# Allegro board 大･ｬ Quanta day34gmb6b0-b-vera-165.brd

Outline 205.8 x 192.8 mm; copper layers: TOP, SGND, IN1, IN2, SVCC, BOTTOM. Coordinates in mm from the lower left corner of the outline.
Outline path: circle c65.95,125.9 r29 ; 0,89.7 0,88.9 arc(0.2,88.29) 0.73,87.94 arc(0.99,87.77) 1.1,87.48 arc(1.19,87.28) 1.4,87.2 3.3,87.2 3.3,87.4 arc(3.45,87.75) 3.8,87.9 7.7,87.9 arc(8.2,88.4) 8.7,87.9 8.7,72.5 arc(8.2,72) 7.7,72.5 3.8,72.5 arc(3.45,72.65) 3.3,73 3.3,73.2 1.4,73.2 arc(1.19,73.12) 1.1,72.92 arc(0.99,72.63) 0.73,72.46 arc(0.2,72.11) 0,71.5 0,70.61 arc(0.29,69.9) 1,69.61 1.8,69.61 arc(2.51,69.32) 2.8,68.61 2.8,68.45 arc(3.09,67.74) 3.8,67.45 11.89,67.45 arc(12.29,67.85) 12.69,67.45 12.69,53.95 arc(12.29,53.55) 11.89,53.95 3.8,53.95 arc(3.09,53.66) 2.8,52.95 2.8,51.45 arc(3.09,50.74) 3.8,50.45 11.89,50.45 arc(12.29,50.85) 12.69,50.45 12.69,36.95 arc(12.29,36.55) 11.89,36.95 3.8,36.95 arc(3.09,36.66) 2.8,35.95 2.8,33.47 arc(3.09,32.76) 3.8,32.47 4.3,32.47 arc(5.01,32.18) 5.3,31.47 5.3,11.97 arc(5.01,11.26) 4.3,10.97 3.8,10.97 arc(3.09,10.68) 2.8,9.97 2.8,8.24 arc(3.03,7.09) 3.68,6.12 8.92,0.88 arc(9.89,0.23) 11.04,0 24.8,0 arc(25.51,0.29) 25.8,1 25.8,4 arc(26.09,4.71) 26.8,5 40.8,5 arc(41.51,5.29) 41.8,6 41.8,8 arc(42.09,8.71) 42.8,9 58.8,9 arc(59.51,8.71) 59.8,8 59.8,3.5 arc(60.09,2.79) 60.8,2.5 97.8,2.5 arc(98.51,2.21) 98.8,1.5 98.8,1 arc(99.09,0.29) 99.8,0 102.8,0 arc(103.51,0.29) 103.8,1 103.8,1.5 arc(104.09,2.21) 104.8,2.5 192.3,2.5 arc(193.01,2.79) 193.3,3.5 193.3,5 arc(193.59,5.71) 194.3,6 201.8,6 arc(204.63,7.17) 205.8,10 205.8,61 202.35,61 202.35,77.25 arc(202.48,77.75) 202.85,78.11 arc(203.22,78.48) 203.35,78.98 203.35,108.4 arc(203.06,109.11) 202.35,109.4 201.5,109.4 201.5,146.79 195.5,146.79 195.5,155.39 201.5,155.39 201.5,164.89 183.85,164.89 183.85,164.39 arc(183.7,164.04) 183.35,163.89 180.95,163.89 arc(180.6,164.04) 180.45,164.39 180.45,164.89 169.9,164.89 169.9,190.8 arc(169.31,192.21) 167.9,192.8 95.8,192.8 arc(94.74,192.36) 94.3,191.3 94.3,189.2 arc(94.01,188.49) 93.3,188.2 86.04,188.2 arc(85.81,188.17) 85.59,188.09 84.35,187.48 arc(83.95,187.11) 83.8,186.58 83.8,185.2 arc(83.51,184.49) 82.8,184.2 80.8,184.2 arc(80.09,184.49) 79.8,185.2 79.8,186.58 arc(79.65,187.11) 79.25,187.48 78.01,188.09 arc(77.79,188.17) 77.56,188.2 69.6,188.2 arc(68.89,187.91) 68.6,187.2 68.6,186.7 arc(68.31,185.99) 67.6,185.7 38.3,185.7 arc(37.59,185.99) 37.3,186.7 37.3,188.5 arc(37.01,189.21) 36.3,189.5 27.3,189.5 arc(26.59,189.21) 26.3,188.5 26.3,181.2 arc(26.01,180.49) 25.3,180.2 17.3,180.2 arc(16.59,180.49) 16.3,181.2 16.3,184.2 arc(16.01,184.91) 15.3,185.2 10.3,185.2 arc(9.59,184.91) 9.3,184.2 9.3,180.6 arc(9.01,179.89) 8.3,179.6 3.8,179.6 arc(3.09,179.31) 2.8,178.6 2.8,177.99 arc(3.09,177.28) 3.8,176.99 10.08,176.99 arc(10.43,176.84) 10.58,176.49 10.58,174.6 arc(10.73,174.25) 11.08,174.1 11.42,174.1 arc(11.77,173.95) 11.92,173.6 11.92,163.8 arc(11.77,163.45) 11.42,163.3 11.08,163.3 arc(10.73,163.15) 10.58,162.8 10.58,160.91 arc(10.43,160.56) 10.08,160.41 3.8,160.41 arc(3.09,160.12) 2.8,159.41 2.8,158.5 arc(3.09,157.79) 3.8,157.5 10.8,157.5 arc(11.51,157.21) 11.8,156.5 11.8,91.7 arc(11.51,90.99) 10.8,90.7 1,90.7 arc(0.29,90.41) 0,89.7

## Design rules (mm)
constraint set DEFAULT: min track width 0.127
net group DFP-S10W10-T12B: nets DDR_THERMDA DDR_THERMDC
net group DFP-S20W10(10)-T12B: nets LINEOUT_L_C LINEOUT_R_C
net group W5-T1B: nets RTC_X1 RTC_X2
net group W20-T1B: nets SMDDR_VREF_DQ0_M3 SMDDR_VREF_DQ1_M3
net group DFP-S4(5)W5(5.5)-T1B: nets C_IN_CLK C_IN_CLK# C_TX0_HDMI+ C_TX0_HDMI- C_TX1_HDMI+ C_TX1_HDMI- C_TX2_HDMI+ C_TX2_HDMI- C_TXC_HDMI+ C_TXC_HDMI- HDMI_SCLK HDMI_SDATA IN_CLK IN_CLK# IN_D0 IN_D0# IN_D1 IN_D1# IN_D2 IN_D2# INT_EDP_AUXN INT_EDP_AUXN_R INT_EDP_AUXP INT_EDP_AUXP_R INT_EDP_TXN0 INT_EDP_TXN0_R INT_EDP_TXN1 INT_EDP_TXN1_R INT_EDP_TXP0 INT_EDP_TXP0_R INT_EDP_TXP1 INT_EDP_TXP1_R PCIE_RXN3_WLAN PCIE_RXN4_LAN PCIE_RXN4_LAN_L PCIE_RXN5_CARD PCIE_RXN5_CARD_C PCIE_RXP3_WLAN PCIE_RXP4_LAN PCIE_RXP4_LAN_L PCIE_RXP5_CARD PCIE_RXP5_CARD_C PCIE_TXN3_WLAN PCIE_TXN3_WLAN_C PCIE_TXN4_LAN PCIE_TXN4_LAN_C PCIE_TXN5_CARD PCIE_TXN5_CARD_C PCIE_TXP3_WLAN PCIE_TXP3_WLAN_C PCIE_TXP4_LAN PCIE_TXP4_LAN_C PCIE_TXP5_CARD PCIE_TXP5_CARD_C SATA_RXN0 SATA_RXN0_17 SATA_RXN1 SATA_RXN1_NG SATA_RXN1_NG_C SATA_RXN1_SSD SATA_RXN2 SATA_RXN2_15 SATA_RXP0 SATA_RXP0_17 SATA_RXP1 SATA_RXP1_NG SATA_RXP1_NG_C SATA_RXP1_SSD SATA_RXP2 SATA_RXP2_15 SATA_TXN0 SATA_TXN0_17 SATA_TXN1 SATA_TXN1_NG SATA_TXN1_NG_C SATA_TXN1_SSD SATA_TXN2 SATA_TXN2_15 SATA_TXP0 SATA_TXP0_17 SATA_TXP1 SATA_TXP1_NG SATA_TXP1_NG_C SATA_TXP1_SSD SATA_TXP2 SATA_TXP2_15 SDVO_CLK SDVO_DATA USB3_1+ USB3_1- USB3_2+ USB3_2- USB3_SSRX+ USB3_SSRX+_DC USB3_SSRX- USB3_SSRX-_DC USB3_SSTX+ USB3_SSTX+_DC USB3_SSTX- USB3_SSTX-_DC USB30_RX1+ USB30_RX1+_C USB30_RX1+_DC USB30_RX1+_L USB30_RX1- USB30_RX1-_C USB30_RX1-_DC USB30_RX1-_L USB30_RX2+ USB30_RX2+_C USB30_RX2- USB30_RX2-_C USB30_RX3+ USB30_RX3+_C USB30_RX3+_DC USB30_RX3- USB30_RX3-_C USB30_RX3-_DC USB30_RX4+ USB30_RX4- USB30_TX1+ USB30_TX1+_C USB30_TX1+_DC USB30_TX1+_L USB30_TX1- USB30_TX1-_C USB30_TX1-_DC USB30_TX1-_L USB30_TX2+ USB30_TX2+_C USB30_TX2- USB30_TX2-_C USB30_TX3+ USB30_TX3+_C USB30_TX3+_DC USB30_TX3+_DC_L USB30_TX3- USB30_TX3-_C USB30_TX3-_DC USB30_TX3-_DC_L USB30_TX4+ USB30_TX4- USBP0+ USBP0+_C USBP0+_CHA USBP0- USBP0-_C USBP0-_CHA USBP1+ USBP1+_C USBP1- USBP1-_C USBP3+ USBP3+_C USBP3- USBP3-_C USBP4+ USBP4+_C USBP4- USBP4-_C USBP5+ USBP5+_C USBP5- USBP5-_C USBP6+ USBP6- USBP7+ USBP7+_C USBP7- USBP7-_C
net group DFP-S4(5)W5(5.5)-T12B: nets M_A_CLKN0 M_A_CLKN1 M_A_CLKP0 M_A_CLKP1 M_A_DQSN0 M_A_DQSN1 M_A_DQSN2 M_A_DQSN3 M_A_DQSN4 M_A_DQSN5 M_A_DQSN6 M_A_DQSN7 M_A_DQSP0 M_A_DQSP1 M_A_DQSP2 M_A_DQSP3 M_A_DQSP4 M_A_DQSP5 M_A_DQSP6 M_A_DQSP7 M_B_CLKN0 M_B_CLKN1 M_B_CLKP0 M_B_CLKP1 M_B_DQSN0 M_B_DQSN1 M_B_DQSN2 M_B_DQSN3 M_B_DQSN4 M_B_DQSN5 M_B_DQSN6 M_B_DQSN7 M_B_DQSP0 M_B_DQSP1 M_B_DQSP2 M_B_DQSP3 M_B_DQSP4 M_B_DQSP5 M_B_DQSP6 M_B_DQSP7
net group DFP-S5(7)W5(5.5)-T1B: nets CK_XDP_N CK_XDP_N_R CK_XDP_P CK_XDP_P_R CLK_PCIE_CRN CLK_PCIE_CRP CLK_PCIE_LANN CLK_PCIE_LANP CLK_PCIE_WLANN CLK_PCIE_WLANP
net group DFP-S10W25-T12B: nets SUB_OUT+ SUB_OUT+_L SUB_OUT+_L_4P SUB_OUT+_L_C SUB_OUT+_R_C SUB_OUT- SUB_OUT-_L SUB_OUT-_L_4P SUB_OUT-_L_C SUB_OUT-_R_C SUB_OUT_LC SUB_OUT_LR SUB_OUT_RC SUB_OUT_RR
net group DFP-S12(15)W5(5.5)-T1B: nets MDI0+ MDI0+_1 MDI0- MDI0-_1 MDI1+ MDI1+_1 MDI1- MDI1-_1 MDI2+ MDI2+_1 MDI2- MDI2-_1 MDI3+ MDI3+_1 MDI3- MDI3-_1
net group W4-T12B: nets LAD0 LAD0_T LAD1 LAD1_T LAD2 LAD2_T LAD3 LAD3_T LFRAME# LFRAME#_T
net group W5(5.5)-T1B: nets ACZ_BCLK BIOS_SPI_CLK BIT_CLK_AUDIO BLON_CON BRIGHT CLK_24M_DEBUG CLK_24M_KBC CLK_PCI_EC_R CLK_PCI_LPC_R CLK_PCI_TPM CLKGEN_RTC_X1 DDR3_DRAMRST# EC_PECI EC_PECI_R EC_PWROK EC_RCIN# GEN_XTAL25_IN GEN_XTAL25_OUT H_CPU_SVIDALRT# H_PROCHOT# H_PROCHOT#_EC LAN_XTAL25_IN LAN_XTAL25_IN_R LVDS_BLON1 MS_BS MS_D0 MS_D1 MS_D2 MS_D3 PCH_SPI1_CLK PCH_SPI1_CLK_R PCH_XTAL24_IN PCH_XTAL24_IN_R PCIE_CLKREQ0# PCIE_CLKREQ1# PCIE_CLKREQ5# PCIE_CLKREQ_CR# PCIE_CLKREQ_LAN# PCIE_CLKREQ_WLAN# PM_THRMTRIP# PN_BLON RSMRST# RTC_RST# SATA_RCOMP SD_CD# SD_CLK_R SD_CMD_R SD_D0_R SD_D1 SD_D1_R SD_D2_R SD_D3_R SRTC_RST# THRM_MOINTOR1 USB_BIAS VADJ1 XTAL1 XTAL2
net group W5(5.5)-T12B: nets ACZ_RST# ACZ_RST#_AUDIO ACZ_SDIN0 ACZ_SDOUT_AUDIO ACZ_SYNC ACZ_SYNC_AUDIO BIOS_CS# BIOS_RD# BIOS_WP# BIOS_WR# DIGITAL_CLK DIGITAL_CLK_L DIGITAL_D1 DMIC_CLK_R DNBSWON# DPWROK DPWROK_EC FAN1_PWM HD_SDIN0 HOLD# IMVP_PWRGD LANRSET M_A_DQ0 M_A_DQ1 M_A_DQ2 M_A_DQ3 M_A_DQ4 M_A_DQ5 M_A_DQ6 M_A_DQ7 M_A_DQ8 M_A_DQ9 M_A_DQ10 M_A_DQ11 M_A_DQ12 M_A_DQ13 M_A_DQ14 M_A_DQ15 M_A_DQ16 M_A_DQ17 M_A_DQ18 M_A_DQ19 M_A_DQ20 M_A_DQ21 M_A_DQ22 M_A_DQ23 M_A_DQ24 M_A_DQ25 M_A_DQ26 M_A_DQ27 M_A_DQ28 M_A_DQ29 M_A_DQ30 M_A_DQ31 M_A_DQ32 M_A_DQ33 M_A_DQ34 M_A_DQ35 M_A_DQ36 M_A_DQ37 M_A_DQ38 M_A_DQ39 M_A_DQ40 M_A_DQ41 M_A_DQ42 M_A_DQ43 M_A_DQ44 M_A_DQ45 M_A_DQ46 M_A_DQ47 M_A_DQ48 M_A_DQ49 M_A_DQ50 M_A_DQ51 M_A_DQ52 M_A_DQ53 M_A_DQ54 M_A_DQ55 M_A_DQ56 M_A_DQ57 M_A_DQ58 M_A_DQ59 M_A_DQ60 M_A_DQ61 M_A_DQ62 M_A_DQ63 M_B_DQ0 M_B_DQ1 M_B_DQ2 M_B_DQ3 M_B_DQ4 M_B_DQ5 M_B_DQ6 M_B_DQ7 M_B_DQ8 M_B_DQ9 M_B_DQ10 M_B_DQ11 M_B_DQ12 M_B_DQ13 M_B_DQ14 M_B_DQ15 M_B_DQ16 M_B_DQ17 M_B_DQ18 M_B_DQ19 M_B_DQ20 M_B_DQ21 M_B_DQ22 M_B_DQ23 M_B_DQ24 M_B_DQ25 M_B_DQ26 M_B_DQ27 M_B_DQ28 M_B_DQ29 M_B_DQ30 M_B_DQ31 M_B_DQ32 M_B_DQ33 M_B_DQ34 M_B_DQ35 M_B_DQ36 M_B_DQ37 M_B_DQ38 M_B_DQ39 M_B_DQ40 M_B_DQ41 M_B_DQ42 M_B_DQ43 M_B_DQ44 M_B_DQ45 M_B_DQ46 M_B_DQ47 M_B_DQ48 M_B_DQ49 M_B_DQ50 M_B_DQ51 M_B_DQ52 M_B_DQ53 M_B_DQ54 M_B_DQ55 M_B_DQ56 M_B_DQ57 M_B_DQ58 M_B_DQ59 M_B_DQ60 M_B_DQ61 M_B_DQ62 M_B_DQ63 MBCLK2 MBCLK3 MBDATA2 MBDATA3 PCH_INVRMEN PCH_SPI1_SI PCH_SPI1_SI_R PCH_SPI1_SO PCH_SPI1_SO_R PCH_SPI_CS0# PCH_SPI_CS0#_R PCH_SPI_IO2 PCH_SPI_IO3 PCIE_WAKE# SM_INTRUDER# SMB_ME1_CLK SMB_ME1_DAT SMB_PCH_CLK SMB_PCH_DAT SMB_RUN_CLK SMB_RUN_DAT SMBALERT# SUSB# SUSC# TPCLK TPCLK-1 TPDATA TPDATA-1 XDP_BPM0 XDP_BPM1
net group W7.5(8.5)-T12B: nets M_A_A0 M_A_A1 M_A_A2 M_A_A3 M_A_A4 M_A_A5 M_A_A6 M_A_A7 M_A_A8 M_A_A9 M_A_A10 M_A_A11 M_A_A12 M_A_A13 M_A_A14 M_A_A15 M_A_BS#0 M_A_BS#1 M_A_BS#2 M_A_CAS# M_A_CKE0 M_A_CKE1 M_A_CS#0 M_A_CS#1 M_A_RAS# M_A_WE# M_B_A0 M_B_A1 M_B_A2 M_B_A3 M_B_A4 M_B_A5 M_B_A6 M_B_A7 M_B_A8 M_B_A9 M_B_A10 M_B_A11 M_B_A12 M_B_A13 M_B_A14 M_B_A15 M_B_BS#0 M_B_BS#1 M_B_BS#2 M_B_CAS# M_B_CKE0 M_B_CKE1 M_B_CS#0 M_B_CS#1 M_B_RAS# M_B_WE#
net group W10(10)-T12B: nets CAP+ CAP- EXT_MIC_L HPOUT_L HPOUT_L_1 HPOUT_R HPOUT_R_1 LINEOUT_L LINEOUT_R MIC_L1 MIC_R1 SENSE_A
net group W10-T12B: nets +SMDDR_VREF_DQ1
net group W12-T1B: nets PCIE_RCOMP SM_RCOMP_0 SM_RCOMP_1 SM_RCOMP_2
net group W15-T12B: nets CFG_RCOMP
net group W20-T12B: nets +SMDDR_VREF_DIMM +SMDDR_VREF_DQ0 EDP_RCOMP
net group W25-T12B: nets L_SPK+ L_SPK+_R L_SPK- L_SPK-_R R_SPK+ R_SPK+_R R_SPK- R_SPK-_R SUB_OUT

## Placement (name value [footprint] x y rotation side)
BAT14  *PMPCRT-08MLBK2ZZ4H0  [BAT-PMPCRT-08MLBK2ZZ4H0-8P-L]  128.55 189.5 0 bottom
BAT15  PMPCRT-08MLBK2ZZ4H1  [BAT-PMPCRT-08MLBK2ZZ4H1-8P-L]  147.8 190.7 0 bottom
BAT17  *196369-20041-3  [88513-2001-20P-L]  151.45 183.55 180 top
C2  22P/50V_4  [CC0402]  43.08 169.22 180 top
C10  *0.047U/25V_4  [CC0402]  58.57 174.62 270 top
C12  *0.047U/25V_4  [CC0402]  59.59 174.62 270 top
C21  0.1U/10V_4  [CC0402]  46.25 179.76 270 bottom
C23  0.1U/25V_4  [CC0402]  63.19 174.62 270 top
C25  1000P/50V_4  [CC0402]  87.91 173.28 90 top
C27  1000P/50V_4  [CC0402]  87.91 167.69 270 top
C28  1000P/50V_4  [CC0402]  18.57 175.18 0 top
C30  1000P/50V_4  [CC0402]  87.91 170.87 270 top
C31  1000P/50V_4  [CC0402]  89.81 169.47 90 top
C32  0.1U/10V_4  [CC0402]  56.03 174.62 270 top
C33  0.1U/10V_4  [CC0402]  57.3 174.62 270 top
C35  0.1U/10V_4  [CC0402]  53.69 172.69 0 top
C36  0.1U/10V_4  [CC0402]  53.69 171.42 0 top
C37  1U/6.3V_4  [CC0402]  51.71 179.38 270 bottom
C40  33P/50V_4  [CC0402]  61.31 175.39 0 top
C48  10U/6.3V_6  [CC0603]  63.52 180.39 180 bottom
C49  0.1U/10V_4  [CC0402]  48.59 182.85 0 top
C50  *220P/50V_4  [CC0402]  35.71 177.22 270 top
C52  0.01U/25V_4  [CC0402]  48.59 179.65 0 top
C58  *220P/50V_4  [CC0402]  32.66 177.22 270 top
C60  *220P/50V_4  [CC0402]  25.68 175.18 0 top
C69  0.1U/10V_4  [CC0402]  30.38 177.22 90 top
C70  0.1U/10V_4  [CC0402]  22.25 172.14 270 top
C71  0.1U/25V_4  [CC0402]  120.11 164.67 90 bottom
C72  0.1U/25V_4  [CC0402]  130.81 164.67 270 bottom
C91  0.01U/25V_4  [CC0402]  129.64 164.67 270 bottom
C92  0.1U/25V_4  [CC0402]  128.45 164.67 270 bottom
C97  0.1U/25V_4  [CC0402]  118.92 164.67 270 bottom
C98  0.1U/25V_4  [CC0402]  124.89 164.67 270 bottom
C101  *4.7U/25V_8  [CC0805]  108.28 164.59 270 bottom
C102  *4.7U/25V_8  [CC0805]  114.83 164.59 270 bottom
C103  0.1U/25V_4  [CC0402]  126.08 164.67 270 bottom
C104  0.1U/25V_4  [CC0402]  127.25 164.67 90 bottom
C105  0.1U/10V_4  [CC0402]  175.03 159.31 270 top
C106  0.1U/10V_4  [CC0402]  171.98 158.93 270 top
C109  *0.1U/10V_4  [CC0402]  173.51 158.67 0 top
C110  0.1U/25V_4  [CC0402]  123.7 164.67 90 bottom
C114  0.1U/25V_4  [CC0402]  122.5 164.67 90 bottom
C115  0.01U/25V_4  [CC0402]  26.85 151.18 0 top
C120  0.1U/25V_4  [CC0402]  121.31 164.67 90 bottom
C125  22U/6.3VS_6  [CC0603]  162.08 97.89 270 top
C175  0.1U/10V_4  [CC0402]  184.12 73.24 180 top
C225  0.1U/10V_4  [CC0402]  19.61 121.16 270 top
C226  0.1U/10V_4  [CC0402]  20.62 121.16 270 top
C227  0.1U/10V_4  [CC0402]  25.04 120.96 180 top
C228  0.1U/10V_4  [CC0402]  27.99 120.37 180 top
C229  *0.1U/25V_4  [CC0402]  187.65 116.31 180 bottom
C230  *0.1U/25V_4  [CC0402]  187.65 117.98 180 bottom
C231  0.1U/10V_4  [CC0402]  17.47 117.04 270 top
C232  0.1U/10V_4  [CC0402]  18.54 117.04 270 top
C233  0.1U/10V_4  [CC0402]  27.4 116.51 270 top
C234  1U/6.3V_4  [CC0402]  28.45 116.51 270 top
C235  1U/6.3V_4  [CC0402]  163.85 115.88 180 top
C236  4.7U/6.3VS_4  [CC0402]  15.85 114.99 270 top
C237  0.1U/10V_4  [CC0402]  18.06 115.49 0 top
C238  22U/6.3V_6  [CC0603]  132.23 113.97 0 top
C239  22U/6.3V_6  [CC0603]  135.41 113.97 180 top
C240  22U/6.3V_6  [CC0603]  138.07 113.97 0 top
C241  22U/6.3V_6  [CC0603]  140.74 113.97 180 top
C242  22U/6.3V_6  [CC0603]  143.79 113.97 0 top
C243  1U/6.3V_4  [CC0402]  163.85 113.97 180 top
C244  0.1U/10V_4  [CC0402]  150.14 113.46 180 top
C245  *12P/50V_4  [CC0402]  152.29 113.46 0 top
C246  *12P/50V_4  [CC0402]  154.34 113.46 180 top
C247  0.1U/10V_4  [CC0402]  27.97 113.08 180 top
C248  *0.1U/10V_4  [CC0402]  15.85 112.95 90 top
C249  4.7U/6.3V_4  [CC0402]  130.43 112.95 270 top
C250  *0.1U/10V_4  [CC0402]  24.15 112.57 180 top
C251  22U/6.3V_6  [CC0603]  132.23 112.45 0 top
C252  22U/6.3V_6  [CC0603]  135.41 112.45 180 top
C253  22U/6.3V_6  [CC0603]  138.07 112.45 0 top
C254  22U/6.3V_6  [CC0603]  140.74 112.45 180 top
C255  22U/6.3V_6  [CC0603]  143.79 112.45 0 top
C256  0.1U/10V_4  [CC0402]  150.14 112.45 180 top
C257  *1U/6.3V_4  [CC0402]  163.85 112.32 180 top
C258  *4.7U/6.3V_6  [CC0603]  28.19 111.81 180 top
C259  *1U/6.3V_4  [CC0402]  24.15 111.56 180 top
C260  *4.7U/6.3V_6  [CC0603]  26.57 110.41 0 top
C261  *10P/50V_4  [CC0402]  24.21 109.86 0 top
C262  *10P/50V_4  [CC0402]  22.55 109.31 270 top
C263  0.1U/10V_4  [CC0402]  16.41 108 90 top
C264  0.1U/10V_4  [CC0402]  17.42 108 90 top
C265  4.7U/6.3VS_4  [CC0402]  18.44 108 90 top
C266  *0.1U/10V_4  [CC0402]  19.75 108.07 90 top
C267  22U/6.3V_6  [CC0603]  135.79 99.75 180 top
C268  22U/6.3V_6  [CC0603]  138.83 99.75 0 top
C269  22U/6.3V_6  [CC0603]  142.26 99.75 180 top
C270  22U/6.3V_6  [CC0603]  145.95 99.75 0 top
C271  22U/6.3V_6  [CC0603]  149.38 99.75 180 top
C272  22U/6.3V_6  [CC0603]  152.68 99.75 0 top
C273  1U/6.3V_4  [CC0402]  160.12 99.57 270 top
C274  10U/6.3VS_6  [CC0603]  156.51 98.83 0 top
C275  22U/6.3V_6  [CC0603]  135.79 98.48 180 top
C276  22U/6.3V_6  [CC0603]  138.83 98.35 0 top
C277  22U/6.3V_6  [CC0603]  142.26 98.35 180 top
C278  22U/6.3V_6  [CC0603]  145.95 98.35 0 top
C279  22U/6.3V_6  [CC0603]  149.38 98.35 180 top
C280  22U/6.3V_6  [CC0603]  152.68 98.35 0 top
C281  *1U/6.3V_4  [CC0402]  156.23 97.59 0 top
C282  1U/6.3V_4  [CC0402]  160.68 97.46 270 top
C283  22U/6.3V_6  [CC0603]  138.83 97.08 0 top
C284  22U/6.3V_6  [CC0603]  142.26 96.95 180 top
C285  22U/6.3V_6  [CC0603]  145.95 96.95 0 top
C286  22U/6.3V_6  [CC0603]  149.38 96.95 180 top
C287  22U/6.3V_6  [CC0603]  152.68 96.95 0 top
C288  1U/6.3V_4  [CC0402]  156.23 96.19 180 top
C289  1U/6.3V_4  [CC0402]  158.35 95.92 90 top
C290  *0.1U/25V_4  [CC0402]  34.06 95.56 90 top
C291  1U/6.3V_4  [CC0402]  162.46 95.17 180 top
C292  0.1U/10V_4  [CC0402]  194.71 95.17 0 top
C293  1U/6.3V_4  [CC0402]  156.18 95.07 0 top
C294  1U/6.3V_4  [CC0402]  160.81 95.02 90 top
C295  22U/6.3V_6  [CC0603]  139.85 94.92 180 top
C296  0.1U/10V_4  [CC0402]  194.71 94.16 0 top
C297  *22P/50V_4  [CC0402]  172.74 92.63 180 bottom
C298  220P/50V_4  [CC0402]  16.38 93.85 270 top
C299  47U/6.3VS_6  [CC0603]  143.53 93.78 90 top
C300  47U/6.3VS_6  [CC0603]  145.57 93.78 90 top
C301  22U/6.3VS_6  [CC0603]  157.25 93.78 180 top
C302  22U/6.3V_6  [CC0603]  139.85 93.52 180 top
C303  *47U/6.3VS_6  [CC0603]  147.64 93.51 90 top
C304  *47U/6.3VS_6  [CC0603]  149.67 93.51 90 top
C305  1U/6.3V_4  [CC0402]  151.41 93.27 90 top
C306  1U/6.3V_4  [CC0402]  152.42 93.27 90 top
C307  0.47U/6.3V_4  [CC0402]  154.46 92.89 90 top
C308  1U/6.3V_4  [CC0402]  160.55 92.89 270 top
C309  1U/6.3V_4  [CC0402]  155.98 92.38 0 top
C310  1U/6.3V_4  [CC0402]  158.01 92.38 0 top
C311  0.1U/10V_4  [CC0402]  162.51 93.27 0 top
C312  22U/6.3V_6  [CC0603]  139.85 92.13 180 top
C313  *0.01U/16V_4  [CC0402]  16.03 91.49 270 top
C314  0.1U/10V_4  [CC0402]  17.04 91.49 270 top
C315  *47P/50V_4  [CC0402]  39.52 91.24 90 top
C316  *1U/6.3V_4  [CC0402]  162.84 91.62 270 top
C317  0.47U/6.3V_4  [CC0402]  161.82 91.62 270 top
C318  *10P/50V_4  [CC0402]  15.77 88.95 270 top
C319  *10P/50V_4  [CC0402]  68.98 87.68 90 top
C320  *10P/50V_4  [CC0402]  70 87.68 90 top
C321  *10P/50V_4  [CC0402]  15.77 86.67 90 top
C322  0.1U/10V_4  [CC0402]  70.51 85.65 270 top
C323  0.1U/10V_4  [CC0402]  71.78 85.65 270 top
C324  0.1U/10V_4  [CC0402]  22.37 84.89 0 top
C325  *1U/6.3V_4  [CC0402]  114.58 84.63 0 top
C326  12P/50V_4  [CC0402]  73.18 83.87 270 top
C327  0.1U/10V_4  [CC0402]  22.37 83.62 0 top
C328  220P/50V_4  [CC0402]  57.17 83.11 270 top
C329  0.1U/10V_4  [CC0402]  39.77 82.98 270 top
C330  *22U/6.3V_6  [CC0603]  114.83 82.98 0 top
C331  0.1U/10V_4  [CC0402]  19.45 82.35 0 top
C332  0.1U/10V_4  [CC0402]  47.52 82.09 270 top
C333  0.1U/10V_4  [CC0402]  43.97 81.71 0 top
C334  0.1U/10V_4  [CC0402]  36.98 81.59 0 top
C335  0.1U/10V_4  [CC0402]  53.24 81.46 0 top
C336  0.1U/10V_4  [CC0402]  19.45 81.08 0 top
C337  15P/50V_4  [CC0402]  73.18 80.95 90 top
C338  0.1U/10V_4  [CC0402]  66.44 80.06 0 top
C339  0.1U/10V_4  [CC0402]  19.45 80.06 0 top
C340  0.1U/10V_4  [CC0402]  73.43 79.3 180 top
C341  470P/50V_4  [CC0402]  24.66 77.75 90 top
C342  1U/10V_4  [CC0402]  34.44 79.12 180 top
C343  0.1U/10V_4  [CC0402]  19.45 78.79 0 top
C344  2.2U/6.3V_4  [CC0402]  71.78 78.41 270 top
C345  0.1U/10V_4  [CC0402]  55.65 78.16 180 top
C346  *0.1U/10V_4  [CC0402]  167.41 78.03 180 top
C347  22U/6.3VS_6  [CC0603]  68.48 77.9 0 top
C349  0.1U/10V_4  [CC0402]  19.45 77.78 0 top
C350  0.1U/10V_4  [CC0402]  34.31 77.27 0 top
C351  *0.1U/25V_4  [CC0402]  142.01 77.14 180 top
C352  *0.1U/10V_4  [CC0402]  69.37 76.76 0 top
C354  0.1U/10V_4  [CC0402]  19.45 76.51 0 top
C355  *0.022U/25V_4  [CC0402]  187.94 77.41 90 top
C356  0.022U/25V_4  [CC0402]  191.41 76.51 180 top
C357  0.1U/10V_4  [CC0402]  34.44 76 0 top
C358  1U/6.3V_4  [CC0402]  169.31 76 180 top
C359  *0.1U/25V_4  [CC0402]  142.01 75.74 180 top
C360  *18P/50V_4  [CC0402]  176.55 74.98 180 top
C361  0.1U/10V_4  [CC0402]  76.86 75.36 270 top
C362  0.1U/10V_4  [CC0402]  78.89 75.36 90 top
C363  1000P/50V_4  [CC0402]  58.44 75.24 180 top
C364  1U/6.3V_4  [CC0402]  165.25 74.98 0 top
C365  *10P/50V_4  [CC0402]  34.47 74.73 0 top
C366  1U/6.3V_4  [CC0402]  58.44 74.22 0 top
C367  1U/6.3V_4  [CC0402]  170.46 73.71 90 top
C368  0.1U/10V_4  [CC0402]  165.25 73.97 0 top
C369  *18P/50V_4  [CC0402]  174.52 76 180 top
C370  0.1U/10V_4  [CC0402]  24.66 99.24 0 top
C371  0.1U/10V_4  [CC0402]  165.25 72.95 0 top
C372  0.1U/10V_4  [CC0402]  15.77 71.93 180 top
C373  *0.1U/10V_4  [CC0402]  174.65 70.92 90 top
C374  1U/6.3V_4  [CC0402]  175.66 70.92 270 top
C375  0.1U/10V_4  [CC0402]  24.66 101.27 180 top
C376  0.1U/10V_4  [CC0402]  56.16 68.63 0 top
C377  0.1U/10V_4  [CC0402]  34.69 67.36 90 top
C378  0.1U/10V_4  [CC0402]  88.67 65.46 270 top
C379  0.1U/10V_4  [CC0402]  34.97 64.47 90 top
C380  0.1U/10V_4  [CC0402]  77.24 64.19 270 top
C381  0.1U/10V_4  [CC0402]  78.26 64.19 270 top
C382  *0.1U/25V_4  [CC0402]  197.11 60 270 top
C383  0.1U/10V_4  [CC0402]  56.16 61.27 0 top
C384  0.1U/10V_4  [CC0402]  169.19 135.43 90 top
C385  0.1U/10V_4  [CC0402]  170.2 135.43 90 top
C386  100P/50V_4  [CC0402]  58.32 60.12 180 top
C387  *33P/50V_4  [CC0402]  185.19 54.66 0 top
C388  *1U/6.3V_4  [CC0402]  190.14 58.98 90 top
C389  0.1U/10V_4  [CC0402]  23.66 58.73 0 top
C390  0.1U/10V_4  [CC0402]  183.89 56.21 270 top
C391  0.1U/10V_4  [CC0402]  23.65 57.71 0 top
C392  *NGFF  [CC0402]  81.68 57.58 270 top
C393  *NGFF  [CC0402]  82.95 57.58 270 top
C394  *33P/50V_4  [CC0402]  189.51 55.8 180 top
C395  0.1U/10V_4  [CC0402]  183.89 58.37 270 top
C396  *Clamp-Diode  [CC0402]  37.21 56.36 270 top
C397  *Clamp-Diode  [CC0402]  35.94 56.36 270 top
C398  10U/6.3V_6  [CC0603]  152.42 50.85 180 top
C399  *NGFF  [CC0402]  74.45 49.96 0 top
C400  *4.7U/6.3V_6  [CC0603]  78.38 49.96 180 top
C401  *0.1U/25V_4  [CC0402]  195.48 49.84 0 top
C402  *NGFF  [CC0402]  64.03 49.71 90 top
C403  *0.01U/16V_4  [CC0402]  85.62 49.71 270 top
C404  *NGFF  [CC0402]  86.64 49.71 270 top
C405  *0.1U/10V_4  [CC0402]  65.56 49.58 0 top
C406  0.22U/50V_8  [CC0805]  186.21 47.35 0 top
C407  0.22U/50V_8  [CC0805]  190.02 47.35 180 top
C408  0.1U/10V_4  [CC0402]  173.12 48.31 0 top
C409  *0.1U/25V_4  [CC0402]  112.55 48.06 270 top
C410  10U/25V_8  [CC0805]  182.01 48.06 0 top
C411  *10U/25V_8  [CC0805]  194.33 48.06 180 top
C412  10U/6.3V_6  [CC0603]  136.04 47.93 90 top
C413  10U/6.3V_6  [CC0603]  140.1 47.93 90 top
C414  10U/6.3V_6  [CC0603]  142.14 47.93 90 top
C415  10U/6.3V_6  [CC0603]  143.66 47.93 90 top
C416  10U/6.3V_6  [CC0603]  146.33 47.93 90 top
C417  0.1U/10V_4  [CC0402]  21.99 47.42 0 top
C418  10U/6.3V_6  [CC0603]  148.11 47.42 90 top
C419  10U/6.3V_6  [CC0603]  150.65 47.42 90 top
C420  0.1U/10V_4  [CC0402]  21.99 46.15 0 top
C421  *10U/25V_8  [CC0805]  182.01 46.03 0 top
C422  10U/25V_8  [CC0805]  194.33 46.03 180 top
C423  10U/6.3V_6  [CC0603]  173.89 44.88 0 top
C424  0.1U/25V_4  [CC0402]  182.14 43.36 0 top
C425  1U/6.3V_4  [CC0402]  172.62 43.31 0 top
C427  1000P/50V_4  [CC0402]  182.14 41.96 0 top
C428  0.1U/25V_4  [CC0402]  194.84 41.96 0 top
C430  1U/6.3V_4  [CC0402]  173 41.45 90 top
C431  1U/6.3V_4  [CC0402]  175.41 41.45 90 top
C432  220P/50V_4  [CC0402]  39.14 41.2 90 top
C433  220P/50V_4  [CC0402]  31.27 40.69 0 top
C434  *0.47U/25V_6  [CC0603]  194.84 40.69 180 top
C435  1000P/50V_4  [CC0402]  182.12 40.56 0 top
C436  *2.2U/6.3V_4  [CC0402]  153.19 39.93 180 top
C437  0.1U/10V_4  [CC0402]  173.76 39.93 0 top
C438  220P/50V_4  [CC0402]  31.27 39.68 0 top
C439  0.1U/25V_4  [CC0402]  194.84 39.42 0 top
C440  0.022U/25V_4  [CC0402]  109.5 39.29 0 top
C441  0.1U/25V_4  [CC0402]  182.12 39.17 0 top
C442  220P/50V_4  [CC0402]  35.58 38.79 180 top
C443  220P/50V_4  [CC0402]  37.74 38.79 0 top
C444  2.2U/6.3V_4  [CC0402]  173.76 38.79 0 top
C446  *0.1U/10V_4  [CC0402]  152.93 38.66 180 top
C447  1U/6.3V_4  [CC0402]  138.53 38.43 0 top
C448  1U/6.3V_4  [CC0402]  140.87 38.41 180 top
C449  1U/6.3V_4  [CC0402]  143.15 38.41 180 top
C450  1U/6.3V_4  [CC0402]  145.44 38.41 180 top
C451  220P/50V_4  [CC0402]  33.55 37.77 180 top
C452  1U/6.3V_4  [CC0402]  140.87 37.14 180 top
C453  1U/6.3V_4  [CC0402]  143.15 37.14 180 top
C454  1U/6.3V_4  [CC0402]  145.44 37.14 180 top
C455  220P/50V_4  [CC0402]  35.58 37.01 180 top
C456  220P/50V_4  [CC0402]  37.74 37.01 0 top
C457  *0.1U/10V_4  [CC0402]  109.5 37.01 180 top
C458  1U/25V_6  [CC0603]  187.6 35.99 180 top
C459  *2.2U/6.3V_4  [CC0402]  109.5 35.74 180 top
C460  1U/25V_6  [CC0603]  194.84 35.61 0 top
C461  220P/50V_4  [CC0402]  36.47 35.48 180 top
C462  220P/50V_4  [CC0402]  38.63 35.48 0 top
C463  *0.1U/10V_4  [CC0402]  36.98 58.5 180 top
C464  1U/25V_6  [CC0603]  190.37 35.07 0 top
C465  1U/6.3V_4  [CC0402]  174.14 34.85 270 top
C466  1U/6.3V_4  [CC0402]  175.16 34.85 270 top
C467  1U/25V_6  [CC0603]  187.6 34.72 180 top
C468  0.022U/25V_4  [CC0402]  113.05 34.47 90 top
C469  *2.2U/6.3V_4  [CC0402]  115.72 34.47 270 top
C470  *0.1U/10V_4  [CC0402]  116.99 34.47 270 top
C471  *0.1U/10V_4  [CC0402]  120.55 34.47 90 top
C472  *0.1U/10V_4  [CC0402]  121.56 34.47 90 top
C473  *10U/25V_8  [CC0805]  181.63 33.2 270 top
C474  1U/6.3V_4  [CC0402]  144.2 34.28 90 top
C475  1U/6.3V_4  [CC0402]  145.47 34.28 90 top
C476  1U/6.3V_4  [CC0402]  146.77 34.25 90 top
C477  10U/6.3V_6  [CC0603]  137.18 34.21 90 top
C478  10U/6.3V_6  [CC0603]  138.58 34.21 90 top
C479  1U/6.3V_4  [CC0402]  140.36 34.21 90 top
C480  1U/6.3V_4  [CC0402]  141.63 34.21 90 top
C481  220P/50V_4  [CC0402]  36.47 33.96 180 top
C482  220P/50V_4  [CC0402]  38.63 33.96 0 top
C483  0.1U/10V_4  [CC0402]  192.17 33.71 0 top
C484  1U/6.3V_4  [CC0402]  172.62 34.34 0 top
C485  0.1U/10V_4  [CC0402]  194.74 33.38 90 top
C486  0.1U/10V_4  [CC0402]  195.88 33.38 90 top
C487  0.1U/10V_4  [CC0402]  192.17 32.69 0 top
C488  220P/50V_4  [CC0402]  36.47 32.44 180 top
C489  220P/50V_4  [CC0402]  38.63 32.44 0 top
C490  10U/6.3V_6  [CC0603]  173.38 33.2 0 top
C491  0.1U/10V_4  [CC0402]  186.59 31.55 90 top
C492  220P/50V_4  [CC0402]  37.74 31.42 0 top
C493  220P/50V_4  [CC0402]  37.74 30.28 0 top
C494  1U/6.3V_4  [CC0402]  176.17 34.85 270 top
C495  1U/6.3V_4  [CC0402]  175.79 33.2 180 top
C496  220P/50V_4  [CC0402]  37.74 29.26 0 top
C497  220P/50V_4  [CC0402]  37.74 28.12 0 top
C498  220P/50V_4  [CC0402]  37.74 27.1 0 top
C499  0.1U/10V_4  [CC0402]  193.78 27.1 270 top
C500  *2.2U/6.3V_4  [CC0402]  153.11 34.98 180 top
C501  10U/6.3V_6  [CC0603]  144.42 26.34 270 top
C502  10U/6.3V_6  [CC0603]  145.69 26.34 270 top
C503  10U/6.3V_6  [CC0603]  146.96 26.34 270 top
C504  10U/6.3V_6  [CC0603]  137.29 26.18 270 top
C505  1U/6.3V_4  [CC0402]  138.58 26.09 270 top
C506  1U/6.3V_4  [CC0402]  139.72 26.09 270 top
C507  1U/6.3V_4  [CC0402]  140.87 26.09 270 top
C508  1U/6.3V_4  [CC0402]  143.15 26.09 270 top
C509  220P/50V_4  [CC0402]  37.74 25.96 0 top
C510  10U/6.3VS_6  [CC0603]  60.22 25.58 0 top
C511  0.1U/10V_4  [CC0402]  63.14 25.58 180 top
C512  0.1U/10V_4  [CC0402]  182.78 26.59 270 top
C513  1U/6.3V_4  [CC0402]  187.49 25.19 180 top
C514  *0_4/S  [SHORT0402]  194.33 25.58 0 top
C515  *0.1U/10V_4  [CC0402]  152.83 33.83 180 top
C516  220P/50V_4  [CC0402]  37.74 24.94 0 top
C517  *AZ2015-01H  [D-SOD523-1_2X0_8-0_7H]  184.17 26.21 90 top
C518  10U/6.3V_6  [CC0603]  36.09 24.84 90 top
C519  0.047U/10V_4  [CC0402]  187.49 24.17 180 top
C520  *0_4/S  [SHORT0402]  194.33 24.56 0 top
C521  *0.01U/16V_4  [CC0402]  111.02 24.31 270 top
C522  220P/50V_4  [CC0402]  37.74 23.8 0 top
C523  *0.1U/10V_4  [CC0402]  86.38 23.67 0 top
C524  *0.1U/10V_4  [CC0402]  74.7 23.29 180 top
C525  4.7U/6.3VS_4  [CC0402]  60.35 23.17 90 top
C526  0.1U/10V_4  [CC0402]  61.49 22.91 90 top
C527  0.1U/10V_4  [CC0402]  64.54 22.91 270 top
C528  *100P/50V_4  [CC0402]  65.81 22.91 90 top
C529  220P/50V_4  [CC0402]  38.63 22.78 0 top
C530  2.2U/6.3V_4  [CC0402]  196.95 22.53 0 top
C531  10U/6.3V_6  [CC0603]  132.23 22.47 90 top
C532  10U/6.3V_6  [CC0603]  133.75 22.47 90 top
C533  0.1U/10V_4  [CC0402]  145.21 22.4 270 top
C534  *2200P/50V_4  [CC0402]  111.02 22.28 90 top
C535  0.1U/10V_4  [CC0402]  182.27 22.15 0 top
C536  *0.1U/10V_4  [CC0402]  36.09 22.15 90 top
C537  0.1U/10V_4  [CC0402]  37.11 22.15 90 top
C538  5.6P/16V_4  [CC0402]  57.17 22.15 270 top
C539  220P/50V_4  [CC0402]  38.63 21.64 0 top
C540  0.022U/25V_4  [CC0402]  153.06 25.58 180 top
C541  0.1U/10V_4  [CC0402]  67.71 21.26 0 top
C542  *10P/50V_4  [CC0402]  88.54 18.34 180 top
C543  10U/6.3VS_6  [CC0603]  182.37 21.03 0 top
C544  10U/6.3VS_6  [CC0603]  180.49 20.8 270 top
C545  0_4  [CC0402]  192.81 20.88 270 top
C546  0_4  [CC0402]  193.95 20.88 270 top
C547  220P/50V_4  [CC0402]  38.63 20.63 0 top
C548  *1U/6.3V_4  [CC0402]  184.22 20.37 270 top
C549  0.1U/10V_4  [CC0402]  67.71 20.24 0 top
C550  10U/6.3VS_6  [CC0603]  182.42 19.86 0 top
C551  1U/10V_4  [CC0402]  57.68 19.61 0 top
C552  220P/50V_4  [CC0402]  38.63 19.48 0 top
C553  10U/6.3VS_6  [CC0603]  189.41 19.3 180 top
C554  *0.1U/10V_4  [CC0402]  74.7 18.97 0 top
C555  10P/50V_4  [CC0402]  178.2 18.17 270 top
C556  0.1U/10V_4  [CC0402]  182.65 18.77 0 top
C557  *0.1U/10V_4  [CC0402]  86.38 18.34 0 top
C558  *2.2U/6.3V_4  [CC0402]  189.38 18.21 0 top
C559  0.1U/10V_4  [CC0402]  189.89 17.2 180 top
C560  10U/6.3VS_6  [CC0603]  177.05 16.61 90 top
C561  *10P/50V_4  [CC0402]  163.6 21.26 270 top
C562  2.2U/6.3V_4  [CC0402]  191.41 16.69 270 top
C563  2.2U/6.3V_4  [CC0402]  192.43 16.69 90 top
C564  0.1U/10V_4  [CC0402]  178.85 16.08 90 top
C565  *10P/50V_4  [CC0402]  163.47 19.23 270 top
C566  10U/6.3VS_6  [CC0603]  147.34 9.58 270 top
C567  0.1U/10V_4  [CC0402]  155.6 11.1 0 top
C568  1U/10V_4  [CC0402]  163.73 12.37 270 top
C569  10P/50V_4  [CC0402]  176.81 14.53 0 top
C570  0.1U/10V_4  [CC0402]  60.73 14.15 0 top
C571  *4.7U/6.3V_4  [CC0402]  191.54 11.86 0 top
C572  10P/50V_4  [CC0402]  162.46 16.69 90 top
C573  4.7U/6.3VS_4  [CC0402]  60.73 13.13 0 top
C574  4.7U/6.3V_4  [CC0402]  191.54 10.72 0 top
C575  10P/50V_4  [CC0402]  162.46 18.72 270 top
C576  1U/6.3V_4  [CC0402]  174.65 13.13 180 top
C577  0.1U/10V_4  [CC0402]  171.6 17.58 180 top
C578  0.1U/10V_4  [CC0402]  178.33 10.85 90 top
C579  1U/10V_4  [CC0402]  146.2 5.89 90 top
C580  0.1U/10V_4  [CC0402]  147.34 5.89 90 top
C581  10U/6.3VS_6  [CC0603]  175.16 11.23 270 top
C582  *0.1U/10V_4  [CC0402]  176.81 9.32 180 top
C583  0.1U/10V_4  [CC0402]  178.46 7.8 270 top
C584  0.1U/10V_4  [CC0402]  180.49 7.8 270 top
C585  *1U/6.3V_4  [CC0402]  185.82 7.8 90 top
C586  0.1U/10V_4  [CC0402]  186.84 7.8 90 top
C587  2.2U/6.3V_4  [CC0402]  187.86 7.8 270 top
C588  10U/6.3VS_6  [CC0603]  182.65 7.42 90 top
C589  0.1U/10V_4  [CC0402]  189.13 7.29 270 top
C590  0.1U/10V_4  [CC0402]  155.22 8.43 180 top
C591  0.1U/10V_4  [CC0402]  158.39 5.13 180 top
C592  0.1U/10V_4  [CC0402]  160.55 5.13 0 top
C593  0.1U/10V_4  [CC0402]  162.71 7.8 270 top
C594  0.01U/25V_4  [CC0402]  179.47 5.77 90 top
C595  10U/6.3VS_6  [CC0603]  183.41 5.39 0 top
C596  10U/6.3VS_6  [CC0603]  188.24 5.26 0 top
C597  *0.1U/10V_4  [CC0402]  146.2 9.58 270 top
C598  0.1U/10V_4  [CC0402]  158.77 14.66 270 top
C599  1U/10V_4  [CC0402]  157.76 14.66 270 top
C608  10P/3KV_1808  [CC1808]  19.58 173.15 270 bottom
C614  1000P/50V_4  [CC0402]  18.57 167.31 0 top
C641  0.1U/25V_4  [CC0402]  116.51 164.65 90 bottom
C644  0.1U/25V_4  [CC0402]  117.73 164.65 90 bottom
C647  *0.01U/16V_4  [CC0402]  175.79 155.07 0 bottom
C649  0.1U/10V_4  [CC0402]  191.57 153.24 90 bottom
C650  10U/6.3VS_6  [CC0603]  173.89 154.28 90 bottom
C651  0.1U/10V_4  [CC0402]  175.79 154.05 0 bottom
C652  *10U/6.3VS_6  [CC0603]  175.89 152.96 0 bottom
C653  0.1U/25V_4  [CC0402]  179.22 153.21 0 bottom
C694  22U/6.3VS_6  [CC0603]  161.44 119.81 90 bottom
C695  22U/6.3VS_6  [CC0603]  162.71 119.81 90 bottom
C696  47U/6.3VS_6  [CC0603]  157.5 119.05 270 bottom
C697  47U/6.3VS_6  [CC0603]  159.54 119.05 270 bottom
C698  0.1U/10V_4  [CC0402]  149.12 115.47 0 bottom
C699  22U/6.3VS_6  [CC0603]  161.44 117.15 90 bottom
C700  22U/6.3VS_6  [CC0603]  162.71 117.15 90 bottom
C701  0.1U/10V_4  [CC0402]  149.12 114.3 0 bottom
C702  *220P/50V_4  [CC0402]  135.58 115.24 90 bottom
C703  *220P/50V_4  [CC0402]  136.73 115.24 90 bottom
C704  0.1U/10V_4  [CC0402]  139.22 115.24 270 bottom
C705  0.1U/10V_4  [CC0402]  149.73 118.47 90 bottom
C706  10U/6.3VS_6  [CC0603]  137.95 114.99 90 bottom
C707  1U/6.3V_4  [CC0402]  157.88 114.86 0 bottom
C708  1U/6.3V_4  [CC0402]  160.17 114.73 270 bottom
C710  1U/6.3V_4  [CC0402]  163.73 114.22 0 bottom
C711  0.1U/10V_4  [CC0402]  148.56 118.47 90 bottom
C712  *0.1U/25V_4  [CC0402]  193.83 107.87 0 bottom
C713  1U/10V_4  [CC0402]  180.87 107.49 270 bottom
C714  0.1U/10V_4  [CC0402]  180.87 105.46 90 bottom
C715  *0.1U/25V_4  [CC0402]  192.17 103.94 0 bottom
C716  22P/50V_4  [CC0402]  188.11 102.67 180 bottom
C717  0.022U/25V_4  [CC0402]  192.56 100.64 180 bottom
C718  *0.1U/10V_4  [CC0402]  120.93 96.57 270 bottom
C719  *10P/50V_4  [CC0402]  113.43 95.68 180 bottom
C720  1U/6.3V_4  [CC0402]  186.08 95.15 90 bottom
C721  10U/6.3VS_6  [CC0603]  194.33 94.54 270 bottom
C722  0.1U/10V_4  [CC0402]  196.49 94.54 270 bottom
C723  0.1U/10V_4  [CC0402]  195.48 94.54 270 bottom
C724  *10P/50V_4  [CC0402]  180.74 92.89 180 bottom
C725  0.1U/10V_4  [CC0402]  194.59 91.87 180 bottom
C726  0.1U/10V_4  [CC0402]  183.41 91.11 180 bottom
C727  *0.01U/25V_4  [CC0402]  194.31 89.1 90 bottom
C728  *0.01U/25V_4  [CC0402]  195.32 89.1 90 bottom
C729  0.01U/25V_4  [CC0402]  194.33 86.52 270 bottom
C730  0.01U/25V_4  [CC0402]  195.35 86.52 270 bottom
C731  0.01U/25V_4  [CC0402]  193.72 82.8 180 bottom
C732  *0.01U/25V_4  [CC0402]  195.98 82.8 0 bottom
C733  0.01U/25V_4  [CC0402]  193.72 81.79 180 bottom
C734  *0.01U/25V_4  [CC0402]  195.98 81.79 0 bottom
C735  22U/6.3V_6  [CC0603]  182.52 80.7 180 bottom
C736  10U/6.3V_6  [CC0603]  144.55 77.39 180 bottom
C737  10U/6.3V_6  [CC0603]  147.34 77.39 0 bottom
C738  10U/6.3V_6  [CC0603]  137.31 77.14 0 bottom
C739  2.2U/6.3V_4  [CC0402]  139.85 77.14 180 bottom
C740  2.2U/6.3V_4  [CC0402]  142.01 77.14 0 bottom
C741  *10P/50V_4  [CC0402]  168.68 76 0 bottom
C742  10U/6.3V_6  [CC0603]  144.55 75.87 180 bottom
C743  10U/6.3V_6  [CC0603]  147.34 75.87 0 bottom
C744  10U/6.3V_6  [CC0603]  137.31 75.74 0 bottom
C745  2.2U/6.3V_4  [CC0402]  139.85 75.74 180 bottom
C746  2.2U/6.3V_4  [CC0402]  142.01 75.74 0 bottom
C747  100U/16V  [ECAP6D3S]  27.71 56.06 90 bottom
C748  *0.1U/25V_4  [CC0402]  88.49 77.47 0 bottom
C749  0.1U/25V_4  [CC0402]  88.47 74.93 0 bottom
C750  *0.01U/16V_4  [CC0402]  81.68 63.3 0 bottom
C751  *0.1U/25V_4  [CC0402]  36.85 62.28 90 bottom
C752  *0.1U/25V_4  [CC0402]  38.89 62.28 90 bottom
C753  *0.1U/25V_4  [CC0402]  42.31 62.28 90 bottom
C754  0.1U/25V_4  [CC0402]  45.36 62.28 90 bottom
C755  0.1U/25V_4  [CC0402]  50.44 62.28 90 bottom
C756  *0.01U/16V_4  [CC0402]  81.68 62.03 0 bottom
C757  *0.01U/16V_4  [CC0402]  81.68 61.01 0 bottom
C758  1000P/50V_4  [CC0402]  18.44 60.76 0 bottom
C759  *0.01U/16V_4  [CC0402]  81.68 59.74 0 bottom
C760  0.1U/10V_4  [CC0402]  18.44 59.61 180 bottom
C761  0.1U/25V_4  [CC0402]  61.11 59.49 180 bottom
C762  0.1U/25V_4  [CC0402]  91.34 59.61 180 bottom
C763  470P/50V_4  [CC0402]  18.44 57.58 180 bottom
C764  100U/16V  [ECAP6D3S]  27.58 48.95 90 bottom
C765  *0.1U/25V_4  [CC0402]  55.27 56.44 180 bottom
C766  0.1U/25V_4  [CC0402]  94.03 58.93 0 bottom
C767  0.1U/10V_4  [CC0402]  18.57 41.33 270 bottom
C768  470P/50V_4  [CC0402]  20.34 51.05 180 bottom
C769  1U/6.3V_4  [CC0402]  20.85 41.33 90 bottom
C770  0.1U/10V_4  [CC0402]  18.06 50.09 0 bottom
C771  *0.1U/25V_4  [CC0402]  26.31 43.1 270 bottom
C772  1000P/50V_4  [CC0402]  20.34 50.04 0 bottom
C773  10U/6.3VS_6  [CC0603]  197.76 43.36 270 top
C774  *0.1U/25V_4  [CC0402]  25.3 43.1 270 bottom
C775  *10U/6.3VS_6  [CC0603]  197.76 46.15 270 top
C776  4.7U/6.3V_6  [CC0603]  27.46 43.36 270 bottom
C777  0.1U/10V_4  [CC0402]  197.51 41.45 0 top
C778  0.01u/25V_4  [CC0402]  94.51 37.26 90 bottom
C779  0.01u/25V_4  [CC0402]  95.53 37.26 90 bottom
C780  0.01u/25V_4  [CC0402]  96.67 37.26 90 bottom
C782  0.01u/25V_4  [CC0402]  97.69 37.26 90 bottom
C786  0.1U/10V_4  [CC0402]  197.13 29.77 270 top
C787  0.1U/10V_4  [CC0402]  34.57 53.9 90 top
C793  0.01U/16V_4  [CC0402]  197.51 40.31 0 top
C794  0.01U/16V_4  [CC0402]  197.51 39.29 0 top
C795  0.01U/16V_4  [CC0402]  197.51 38.28 0 top
C796  0.01U/16V_4  [CC0402]  197.51 37.26 0 top
C797  1U/10V_4  [CC0402]  190.78 20.75 270 bottom
C798  1U/10V_4  [CC0402]  191.79 20.88 270 bottom
C799  1U/10V_4  [CC0402]  194.97 20.88 270 bottom
C800  1U/10V_4  [CC0402]  195.98 20.88 270 bottom
C801  1U/10V_6  [CC0603]  190.02 18.44 270 bottom
C802  1U/25V_6  [CC0603]  191.29 18.44 270 bottom
C803  1U/10V_4  [CC0402]  190.9 16.56 0 bottom
C804  1U/10V_4  [CC0402]  190.9 15.55 180 bottom
C805  *1000P/50V_4  [CC0402]  191.41 14.02 180 bottom
C806  *1000P/50V_4  [CC0402]  198.27 14.02 0 bottom
C810  *22U/6.3V_6  [CC0603]  68.55 174.34 90 top
C1027  *2.2U/6.3V_6  [CC0603]  148.49 5.89 270 top
C1028  *1U/10V_4  [CC0402]  143.53 5.26 180 top
C7747  *0.1U/10V_4  [CC0402]  44.6 179.25 0 bottom
C7748  *0.022U/16V_4  [CC0402]  45.11 181.92 0 bottom
C8738  0_4  [CC0402]  164.62 5.13 0 top
C8739  Clamp-Diode  [CC0402]  17.9 37.21 270 bottom
C8742  33P/50V_4  [CC0402]  63.19 172.57 90 top
C8743  *10P/50V_4  [CC0402]  185.9 151.72 0 top
C8744  *10P/50V_4  [CC0402]  183.74 150.47 0 top
C8745  *0_4  [RC0402]  72.49 172.59 90 top
C8746  *0.1U/10V_4  [CC0402]  73.15 164.01 0 bottom
C8774  *0_4  [RC0402]  71.22 172.59 90 top
C8775  *0_4  [RC0402]  69.95 172.59 90 top
C8776  0.1U/10V_4  [CC0402]  185.9 152.97 0 top
C8777  *4.7U/6.3V_4  [CC0402]  64.46 176.96 270 bottom
C8778  *0.01U/16V_4  [CC0402]  63.24 176.96 270 bottom
C8779  0.1U/10V_4  [CC0402]  52.09 173.96 0 top
C8780  0.1U/10V_4  [CC0402]  52.09 175.23 0 top
C8781  0.1U/10V_4  [CC0402]  58.47 171.02 180 top
C8782  *0.1U/10V_4  [CC0402]  73.15 162.81 0 bottom
C8783  *0.1U/10V_4  [CC0402]  73.15 165.46 0 bottom
C8784  0.1U/10V_4  [CC0402]  67.82 165.33 0 top
C8785  *0.1U/10V_4  [CC0402]  73.15 166.65 0 bottom
C8786  *0_4  [RC0402]  73.76 172.59 90 top
CN2  51540-0400T-001  [51540-0404T-001-40P-L]  63.1 181 180 top
CN3  INT SPEAKER CONN  [88266-0400-4P-L]  102.2 172.17 270 top
CN5  POWER BTN CONN  [88513-0601-6P-L-SMT]  33.3 171.63 0 top
CN6  88266-020L  [88266-020L-2P-L-SMT]  194.9 127.95 90 top
CN8  *SEC_BSH-030-01-L-D-A-TR  [BSH-030-01-L-D-A-TR-60P-LDH]  73.81 69.77 180 top
CN9  *ACES_88511-180N  [88511-180N-18P-L]  170.33 65.2 270 top
CN10  KB_LIGHT_CONN_15"  [50505-0040N-V01-4P-L]  176.4 137.4 90 top
CN11  *Leap Motion  [50519-00801-V01-8P-L]  202.05 53.65 90 top
CN12  POWER BTN CONN  [88513-0601-6P-L-SMT]  42.9 56 90 top
CN13  KB CONN  [51586-03241-001-32P-L]  43.75 30 90 top
CN14  SMD FPC 30P  [50501-03001-001-30P-L]  201.92 22.5 90 top
CN15  CARDREADER CONN  [SDCARD-PSDBTC-09GLBS1NN4H3-11P]  19.05 20.9 270 top
CN16  POWER BTN CONN  [88513-0601-6P-L-SMT]  173.75 22.35 180 top
CN17  4P Subwoofer CONN  [50281-00401-001-4P-L]  75.68 7.75 270 top
CN20  DC-IN CONN  [59012-0080N-003-8P-LDV-SMT]  31.8 181.01 180 bottom
CN21  RJ45_CONN  [RJ45-60414-08G67-12P]  5.72 168.7 90 bottom
CN22  MINI PCIE H=4.0  [MINIPCI-80053-1023-52P-SMT]  186 160.31 0 bottom
CN24  HDMI CONN  [HDMI-HMRBL-AK520C-19P]  2.1 80.2 90 bottom
CN25  USB3.0 CONN  [USB-YUSB0015-P002A-9P]  5.93 60.7 90 bottom
CN26  *MINI PCIE H4  [MINICARD-110021-52131-52P-RUV]  75.45 53.5 180 bottom
CN27  BAT_CONN  [BAT-23_2-4_2]  193.45 45.8 90 bottom
CN28  USB3.0 CONN  [USB-YUSB0015-P002A-9P]  5.93 43.7 90 bottom
CN29  SSD_NGFF_CONN_75P  [MIPCI-APCI0020-P003H-75P-KM]  96.8 24.2 270 bottom
CN31  INT SPEAKER CONN  [88266-0400-4P-L]  193.1 151.09 90 top
D1  MEK500V-40  [DSM]  41.81 172.01 180 top
D2  RB501V-40  [DSM]  112.93 93.52 90 top
D3  RB500V-40  [DSM]  20.72 88.95 0 top
D4  MEK500V-40  [DSM]  50.06 86.67 270 top
D5  RB500V-40  [DSM]  20.72 86.67 0 top
D6  MEK500V-40  [DSM]  32.18 86 270 top
D7  PDZ5.6B  [DSM]  59.59 64.14 0 top
D8  *1SS355  [DSM]  59.59 62.24 180 top
D9  *BAT54C  [SOT323_213-2_1-1_3-2N7002W]  192.81 58.6 0 top
D10  RB500V-40  [DSM]  184.88 60.4 180 top
D11  MEK500V-40  [DSM]  169.44 15.04 0 top
D13  BAT54A-7-F  [SOT323_213-2_1-1_3-3P]  201.01 16.56 0 bottom
D14  BAT54A-7-F  [SOT323_213-2_1-1_3-3P]  165.63 13.89 90 top
EC1  0.1U/25V_4  [CC0402]  71.07 178.46 180 bottom
EC2  1000P/50V_4  [CC0402]  31.9 177.47 180 bottom
EC3  *100P/50V_4  [CC0402]  65.53 174.62 270 top
EC4  *680P/50V_4  [CC0402]  25.68 173.91 0 top
EC5  0.1U/10V_4  [CC0402]  31.52 177.22 90 top
EC6  *1U/25V_4  [CC0402]  99.87 175.08 90 bottom
EC7  *1U/25V_4  [CC0402]  98.86 175.08 90 bottom
EC8  *1U/25V_4  [CC0402]  100.89 175.08 90 bottom
EC9  *1U/25V_4  [CC0402]  97.84 175.08 90 bottom
EC10  *33P/50V_4  [CC0402]  184.02 158.7 0 top
EC11  10U/25V_8  [CC0805]  106.09 164.59 270 bottom
EC12  *220P/50V_4  [CC0402]  173.63 153.72 180 top
EC13  *220P/50V_4  [CC0402]  171.6 153.7 180 top
EC14  10U/25V_8  [CC0805]  103.91 164.59 270 bottom
EC15  10U/25V_8  [CC0805]  110.46 164.59 270 bottom
EC16  10U/25V_8  [CC0805]  112.65 164.59 270 bottom
EC17  *1000P/50V_4  [CC0402]  181.18 152.37 270 bottom
EC18  *1000P/50V_4  [CC0402]  182.19 152.37 270 bottom
EC19  *68P/50V_4  [CC0402]  20.98 149.4 90 top
EC20  680P/50V_4  [CC0402]  189.63 130.1 0 top
EC21  680P/50V_4  [CC0402]  189.63 125.65 0 top
EC22  *0.1U/25V_4  [CC0402]  23.01 93.27 0 top
EC23  *1000P/50V_4  [CC0402]  39.52 92.76 0 top
EC24  *220P/50V_4  [CC0402]  32.54 90.73 90 top
EC25  *220P/50V_4  [CC0402]  41.55 81.84 180 top
EC26  18P/50V_4  [CC0402]  160.3 76.25 270 top
EC27  *18P/50V_4  [CC0402]  161.44 76.51 270 top
EC28  *1000P/50V_4  [CC0402]  61.11 76.38 180 top
EC29  18P/50V_4  [CC0402]  162.96 74.98 180 top
EC30  0.1U/10V_4  [CC0402]  18.95 74.85 270 top
EC31  *120P/50V_4  [CC0402]  152.55 48.18 180 top
EC32  *120P/50V_4  [CC0402]  174.39 41.45 90 top
EC33  *0.1U/10V_4  [CC0402]  136.7 37.88 270 top
EC34  *120P/50V_4  [CC0402]  148.49 37.75 270 top
EC35  *120P/50V_4  [CC0402]  138.53 37.16 0 top
EC36  *120P/50V_4  [CC0402]  149.85 37.05 270 top
EC37  10U/6.3VS_6  [CC0603]  91.08 22.78 90 top
EC38  *120P/50V_4  [CC0402]  172.62 35.36 0 top
EC39  *0.1U/10V_4  [CC0402]  148.09 34.29 90 top
EC40  *0.1U/10V_4  [CC0402]  142.77 34.21 90 top
EC41  5.6P/16V_4  [CC0402]  35.96 30.79 270 top
EC42  470p/50V/X7R_4  [CC0402]  92.1 37.77 90 bottom
EC43  *120P/50V_4  [CC0402]  135.41 28.88 180 top
EC44  5.6P/16V_4  [CC0402]  35.96 28.49 90 top
EC45  10U/6.3VS_6  [CC0603]  93.24 38.02 90 bottom
EC46  *0.1U/10V_4  [CC0402]  136.07 26.15 270 top
EC47  *120P/50V_4  [CC0402]  134.9 26.09 270 top
EC48  *120P/50V_4  [CC0402]  142.01 26.09 270 top
EC49  *0.1U/25V_4  [CC0402]  97.43 25.32 90 top
EC50  *220P/50V_4  [CC0402]  88.03 23.04 270 top
EC51  120P/50V_4  [CC0402]  127.66 22.21 90 top
EC52  *120P/50V_4  [CC0402]  129.31 22.21 90 top
EC53  *120P/50V_4  [CC0402]  130.83 22.21 90 top
EC54  1000P/50V_4  [CC0402]  189.84 21.11 270 top
EC55  *220P/50V_4  [CC0402]  197.25 20.88 270 top
EC56  *220P/50V_4  [CC0402]  36.09 17.59 270 top
EC57  *0.1U/25V_4  [CC0402]  94.51 16.31 0 top
EC58  *220P/50V_4  [CC0402]  65.94 14.53 90 top
EC59  *220P/50V_4  [CC0402]  75.21 16.82 270 top
EC60  *33P/50V_4  [CC0402]  176.3 11.99 270 top
EC61  *10P/50V_4  [CC0402]  176.81 13.51 180 top
EC62  *33P/50V_4  [CC0402]  178.84 13.39 0 top
EC63  680P/50V_4  [CC0402]  81.68 11.63 90 top
EC64  680P/50V_4  [CC0402]  92.48 5.64 90 bottom
EC65  *10P/50V_4  [CC0402]  176.81 10.47 0 top
EC66  680P/50V_4  [CC0402]  92.46 7.78 270 bottom
EC67  5.6P/16V_4  [CC0402]  35.57 10.72 0 top
EC68  680P/50V_4  [CC0402]  83.23 10.59 0 top
EC69  1000P/50V_4  [CC0402]  178.97 9.32 0 top
EC70  5.6P/16V_4  [CC0402]  35.57 9.7 0 top
EC71  *220P/50V_4  [CC0402]  35.57 7.54 0 top
EC73  680P/50V_4  [CC0402]  186.97 45.64 0 top
EC74  680P/50V_4  [CC0402]  189.63 45.77 180 top
EC75  *220P/50V_4  [CC0402]  194.74 102.84 180 bottom
EC76  *220P/50V_4  [CC0402]  192.56 99.37 0 bottom
EC77  *1000P/50V_4  [CC0402]  54.43 58.06 90 bottom
EC78  *680P/50V_4  [CC0402]  202.21 27.61 90 bottom
EC79  *680P/50V_4  [CC0402]  200.84 27.61 90 bottom
EC80  1000P/50V_4  [CC0402]  199.03 18.47 270 bottom
EC81  1000P/50V_4  [CC0402]  187.32 14.38 0 bottom
EC82  1000P/50V_4  [CC0402]  200.94 12.62 180 bottom
EC84  4.7U/25V_8  [CC0805]  139.34 181.78 0 top
EC85  *0.1U/25V_4  [CC0402]  139.36 183.29 180 top
EC86  *4.7U/25V_8  [CC0805]  139.34 179.71 0 top
EC87  1000P/50V_4  [CC0402]  150.14 6.02 0 top
EC88  1000P/50V_4  [CC0402]  170.46 6.53 270 top
EC89  1000P/50V_4  [CC0402]  171.73 6.53 270 top
EC90  1000P/50V_4  [CC0402]  168.5 6.58 270 top
EC91  1000P/50V_4  [CC0402]  150.14 8.05 0 top
EC92  1000P/50V_4  [CC0402]  150.14 7.04 0 top
F1  FUSE1A6V_POLY  [FSMD1206P150TS]  20.34 91.11 0 top
FAN1  FAN Connect  [50273-0040L-001-4P-L]  136.79 117.98 180 bottom
H1  *H-TC236BC315D118P2  [H-TC236BC315D118P2]  111.8 190 0 top
H2  *O-U83B-5  [O-U83B-5]  166.8 190 0 top
H3  *H-TC236BC315D118P2  [H-TC236BC315D118P2]  99.8 189 0 top
H5  *H-TC276BC197D142P2  [H-TC276BC197D142P2]  143.92 172.93 0 top
H7  -  [H-C236D146P2]  37.8 158.48 180 bottom
H8  *H-C98D98N  [H-C98D98N]  107.6 112.5 0 top
H9  *O-U83B-4  [O-U83B-4]  197.8 137.4 0 top
H10  *H-TC276BC197D142P2  [H-TC276BC197D142P2]  124.83 126.25 0 top
H11  *H-TC276BC197D142P2  [H-TC276BC197D142P2]  163.01 126.25 0 top
H12  *O-U83A-1  [O-U83A-1]  65.95 125.9 0 top
H13  *H-C236D118P2  [H-C236D118P2]  111.85 122.7 0 top
H14  *INTEL-BKT-SHARK-ULT  [INTEL-BKT-SHARK-ULT]  148.6 96.2 180 top
H15  *H-TC256IC118BC315D118P2  [H-TC256IC118BC315D118P2]  188.5 86.54 0 top
H16  *H-C236D102P2  [H-TC236IC102BC236D102P2]  200.1 74 0 top
H18  *O-Y12A-5  [O-Y12A-5]  23.8 65.5 0 top
H19  *H-C394D354P2  [H-C394D354P2]  98.8 65.5 0 top
H20  -  [H-TC177BC197D102P2]  18.55 24.2 180 bottom
H22  *H-TC236BC102D102P2  [H-TC236BC102D102PT]  63.36 5.65 180 bottom
H23  *o-y11-1  [O-Y11-1]  20.8 2.65 0 top
H26  *O-Y12A-7  [O-Y12A-7]  101.3 2.8 0 top
H27  *o-y11a-2  [O-Y11A-2]  192.99 7.23 0 top
H28  *O-Y12A-4  [O-Y12A-4]  12.8 182.2 0 top
HD17  17 SATA ODD  [51625-01001-001-10P-L]  202.9 39.5 90 top
J1  *SOLDERJUMPER-2  [SOLDERJUMPER-2]  174.42 76.48 315 bottom
JDIM1  DDR3-DIMM1_H=4.0_RVS  [DDR-DDRRK-20401-TP4B-204P-RUV]  144 43.55 180 bottom
JDIM2  DDR3-DIMM0_H=4.0_STD  [DDR-DDRSK-20401-TP4B-204P-LDV]  144 30.15 0 bottom
L3  TI160808U600  [RC0603]  85.88 172.9 0 top
L4  TI160808U600  [RC0603]  85.88 171.5 0 top
L5  TI160808U600  [RC0603]  85.88 170.1 0 top
L6  TI160808U600  [RC0603]  85.88 168.71 0 top
L7  MCM2012B900GBE  [CHOKE-WCM2012-4P]  67.08 174.07 270 top
L8  0_6  [RC0603]  58.58 181.79 0 bottom
L12  PBY160808T-151Y-N  [RC0603]  191.79 132.39 0 top
L14  PBY160808T-151Y-N  [RC0603]  191.29 123.5 0 top
L15  4.7UH,+-20%,650MA_1210  [CHOKE-LQH32PN4R7NN0L]  18.29 110.62 180 top
L16  2.2uH/500mA_6  [RC0603]  141.76 94.16 90 top
L17  *HCB1608KF-181T15/S  [SHORT0603]  34.72 86 270 top
L18  *HCB1608KF-181T15/S  [SHORT0603]  58.7 76.38 180 top
L19  *BLM18BA470SN1D/S  [SHORT0603]  56.41 72.82 90 top
L22  *DLP11SN900HL2L  [CHOKE-WCM2012-4P]  194.28 53.85 0 top
L25  HCB1005KF-181T15(180,1.5A)_4  [RC0402]  192.94 49.68 0 top
L27  DLP11SN900HL2L  [CHOKE-WCM2012-4P]  19.58 44.12 180 top
L29  MCM2012B900GBE  [CHOKE-WCM2012-4P]  197.51 32.69 270 top
L30  HCB1005KF-181T15  [RC0402]  182.78 24.18 90 top
L31  HCB1005KF-181T15  [RC0402]  188.75 21.39 270 top
L32  *HCB1005KF-181T15  [RC0402]  175.41 16.82 180 top
L33  HCB1005KF-181T15  [RC0402]  175.41 15.8 180 top
L34  HCB1005KF-181T15(180,1.5A)_4  [RC0402]  148.49 8.31 270 top
L35  BLM18BA470SN1D  [RC0402]  160.93 17.2 180 top
L36  PBY160808T-151Y-N  [RC0603]  94.43 6.05 0 bottom
L37  HCB1005KF-181T15  [RC0402]  173.89 11.23 90 top
L38  BLM18BA470SN1D  [RC0402]  160.93 18.21 180 top
L39  PBY160808T-151Y-N  [RC0603]  94.43 7.27 0 bottom
L40  PBY160808T-151Y-N  [RC0603]  85.75 11.89 0 top
L41  PBY160808T-151Y-N  [RC0603]  85.75 10.69 0 top
L42  HCB1005KF-181T15(180,1.5A)_4  [RC0402]  156.23 14.15 0 top
L44  2.2uH/500mA_6  [RC0603]  163.98 119.81 270 bottom
L45  2.2uH/500mA_6  [RC0603]  163.98 117.15 90 bottom
L46  2.2uH/500mA_6  [RC0603]  159.15 116.64 0 bottom
L47  HCB1005KF-181T15(180,1.5A)_4  [RC0402]  200.94 13.77 180 bottom
L58  0_4  [RC0402]  185.93 150.47 0 top
L59  0_8  [RC0805]  63.3 174.07 270 bottom
L60  *0_8  [RC0805]  65.45 174.07 270 bottom
NOREF  -  []  173.25 -28.02 0 top
NOREF#2  -  [unnamed#2]  196.7 13.64 0 top
NOREF#3  -  [unnamed#2]  164.26 182.42 0 top
NOREF#4  -  []  31.67 104.09 270 top
NOREF#5  -  []  11.45 -37.29 0 top
NOREF#6  -  [unnamed#2]  22.38 176.96 0 top
NOREF#7  -  [unnamed#2]  202.59 24.82 180 bottom
NOREF#8  -  [unnamed#2]  27.33 177.47 180 bottom
NOREF#9  -  []  14.42 13.8 0 bottom
NOREF#10  -  [unnamed#2]  6.22 8.1 180 bottom
ODD14  *14 SATA ODD  [SATA-202407-2-13P-R]  201.55 94.04 270 bottom
ODD15  15 SATA ODD  [51605-01801-001-18P-L]  196 85.8 90 top
PC1  0.01U/25V_4  [CC0402]  130.96 186.23 270 top
PC5  0.1U/25V_4  [CC0402]  34.31 177.47 180 bottom
PC7  0.1U/25V_4  [CC0402]  92.38 185.09 180 top
PC9  0.1U/25V_4  [CC0402]  94.46 184.79 180 top
PC10  *100P/50V_4  [CC0402]  124.48 185.73 180 top
PC11  *100P/50V_4  [CC0402]  126.64 185.73 0 top
PC12  4.7U/25V_8  [CC0805]  102.79 182.55 180 top
PC13  0.47U/25V_6  [CC0603]  94.23 182.98 270 top
PC34  0.1U/10V_4  [CC0402]  174.01 125.27 270 top
PC35  0.1U/10V_4  [CC0402]  175.03 125.27 270 top
PC37  0.01U/25V_4  [CC0402]  176.81 118.42 90 top
PC38  *10U/6.3V_6  [CC0603]  174.9 118.03 180 top
PC39  0.1U/10V_4  [CC0402]  163.85 117.91 0 top
PC41  *22U/6.3V_8  [CC0805]  112.29 99.62 90 top
PC42  *22U/6.3V_8  [CC0805]  114.7 99.62 90 top
PC43  *22U/6.3V_8  [CC0805]  117.07 99.67 90 top
PC44  *22U/6.3V_8  [CC0805]  119.4 99.62 90 top
PC45  1000P/50V_4  [CC0402]  28.37 175.85 0 bottom
PC46  1000P/50V_4  [CC0402]  30.27 176.08 270 bottom
PC47  *22U/6.3V_8  [CC0805]  137.51 93.83 270 top
PC48  4.7U/25V_8  [CC0805]  100.48 91.75 270 bottom
PC49  4.7U/25V_8  [CC0805]  102.51 91.75 270 bottom
PC50  0.1U/25V_4  [CC0402]  98.96 90.98 270 top
PC51  0.22U/25V_6  [CC0603]  97.05 88.82 270 top
PC52  2.2U/10V_6  [CC0603]  89.81 88.32 90 top
PC53  1000P/50V_4  [CC0402]  89.3 85.4 180 top
PC54  220P/50V_4  [CC0402]  88.25 83.87 270 top
PC55  1500P/50V_4  [CC0402]  89.27 83.87 270 top
PC56  470P/50V_4  [CC0402]  91.59 82.47 180 bottom
PC57  0.1U/10V_4  [CC0402]  100.86 81.33 180 top
PC58  10P/50V_4  [CC0402]  90.7 79.17 0 top
PC59  *2200P/50V_4  [CC0402]  95.27 78.66 270 top
PC60  1000P/50V_4  [CC0402]  96.29 78.66 270 top
PC61  1U/6.3V_4  [CC0402]  94.64 81.46 90 bottom
PC62  *1500P/50V_4  [CC0402]  91.21 77.65 90 top
PC63  330P/50V_4  [CC0402]  92.73 77.14 0 top
PC64  10U/6.3V_6  [CC0603]  180.49 68.25 270 top
PC65  0.1U/10V_4  [CC0402]  179.22 68.12 90 top
PC66  0.1U/10V_4  [CC0402]  56.16 66.09 180 top
PC67  0.01U/25V_4  [CC0402]  58.44 66.09 180 top
PC68  0.01U/50V_4  [CC0402]  56.16 64.95 180 top
PC69  0.1U/25V_4  [CC0402]  197.25 64.57 0 top
PC70  4.7U/25V_8  [CC0805]  194.33 64.24 0 top
PC71  0.1U/10V_4  [CC0402]  189.51 63.93 270 top
PC72  0.1U/25V_4  [CC0402]  198.13 60 90 top
PC73  2200P/50V_4  [CC0402]  197.25 63.55 0 top
PC74  4.7U/6.3V_6  [CC0603]  184.05 62.54 0 top
PC75  *22U/6.3V_8  [CC0805]  102 53.52 0 top
